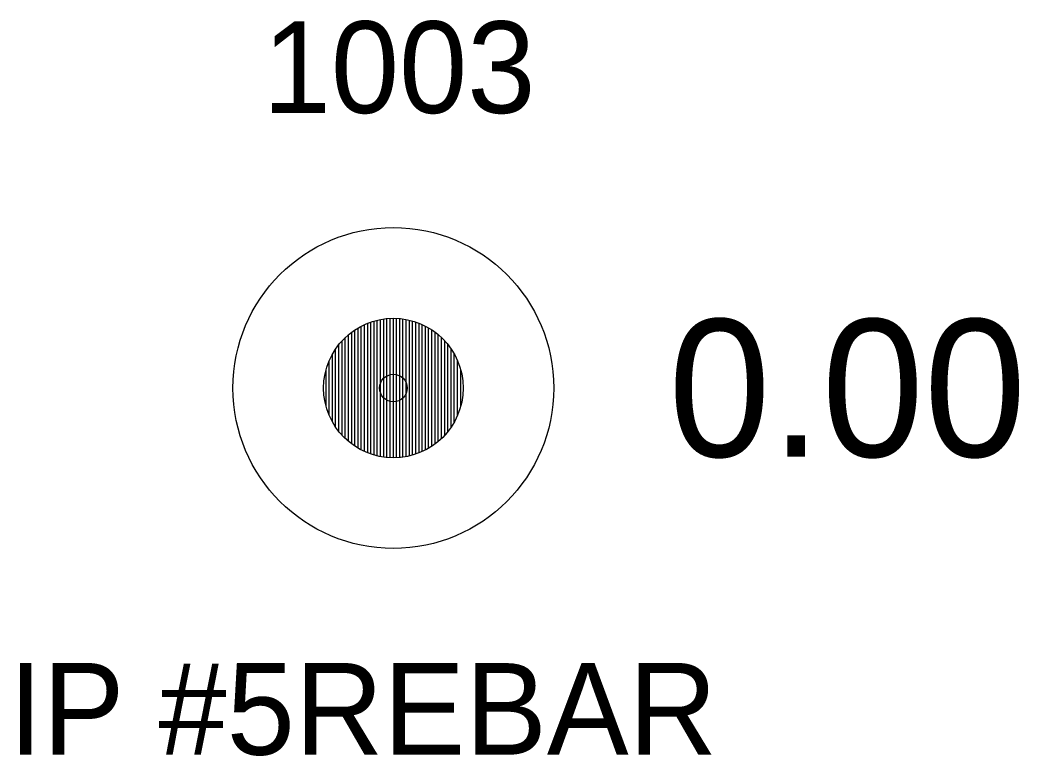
# Model space of a CAD drawing. Extents: x 2449052 to 2452984, y 1012343 to 1015262.
# Drawn here: x 2449337.72 to 2449348.62, y 1012428.52 to 1012436.55 of the extents above; entities that cross this region are included whole.
import ezdxf

# ---------------------------------------------------------------- set-up
doc = ezdxf.new("R2010")
doc.units = 0
for name, color, linetype in [('RD_EX_DV_Prop_txCode', 7, 'Continuous'), ('RD_EX_DV_PropPin', 7, 'Continuous'), ('RD_EX_TX_DV_Prop_ELEV', 7, 'Continuous'), ('RD_SMD_Locator', 7, 'Continuous')]:
    doc.layers.add(name, color=color, linetype=linetype)

msp = doc.modelspace()

# ---------------------------------------------------------------- linework, layer by layer
at = {"layer": 'RD_EX_DV_PropPin'}
for p, q in [((2449341.79, 1012431.773), (2449341.79, 1012433.295)), ((2449341.405, 1012431.877), (2449341.405, 1012433.19)), ((2449341.44, 1012431.858), (2449341.44, 1012433.209)), ((2449341.475, 1012431.841), (2449341.475, 1012433.227)), ((2449341.51, 1012431.826), (2449341.51, 1012433.241)), ((2449341.545, 1012431.813), (2449341.545, 1012433.254)), ((2449341.58, 1012431.802), (2449341.58, 1012433.265)), ((2449341.615, 1012431.793), (2449341.615, 1012433.274)), ((2449341.65, 1012431.786), (2449341.65, 1012433.282)), ((2449341.685, 1012431.78), (2449341.685, 1012433.288)), ((2449341.72, 1012431.776), (2449341.72, 1012433.292)), ((2449341.755, 1012431.774), (2449341.755, 1012433.294)), ((2449341.825, 1012431.774), (2449341.825, 1012433.294)), ((2449341.86, 1012431.776), (2449341.86, 1012433.292)), ((2449341.895, 1012431.78), (2449341.895, 1012433.288)), ((2449341.93, 1012431.786), (2449341.93, 1012433.282)), ((2449341.965, 1012431.793), (2449341.965, 1012433.274)), ((2449342, 1012431.802), (2449342, 1012433.265)), ((2449342.035, 1012431.813), (2449342.035, 1012433.254)), ((2449342.07, 1012431.826), (2449342.07, 1012433.241)), ((2449342.105, 1012431.841), (2449342.105, 1012433.227)), ((2449342.14, 1012431.858), (2449342.14, 1012433.209)), ((2449342.175, 1012431.877), (2449342.175, 1012433.19)), ((2449341.265, 1012431.983), (2449341.265, 1012433.085)), ((2449341.3, 1012431.952), (2449341.3, 1012433.116)), ((2449341.335, 1012431.924), (2449341.335, 1012433.144)), ((2449341.37, 1012431.899), (2449341.37, 1012433.168)), ((2449342.21, 1012431.899), (2449342.21, 1012433.168)), ((2449342.245, 1012431.924), (2449342.245, 1012433.144)), ((2449342.28, 1012431.952), (2449342.28, 1012433.116)), ((2449342.315, 1012431.983), (2449342.315, 1012433.085)), ((2449341.195, 1012432.06), (2449341.195, 1012433.008)), ((2449341.23, 1012432.019), (2449341.23, 1012433.049)), ((2449342.35, 1012432.019), (2449342.35, 1012433.049)), ((2449342.385, 1012432.06), (2449342.385, 1012433.008)), ((2449341.125, 1012432.164), (2449341.125, 1012432.903)), ((2449341.16, 1012432.107), (2449341.16, 1012432.96)), ((2449342.42, 1012432.107), (2449342.42, 1012432.96)), ((2449342.455, 1012432.164), (2449342.455, 1012432.903)), ((2449341.09, 1012432.236), (2449341.09, 1012432.832)), ((2449342.49, 1012432.236), (2449342.49, 1012432.832)), ((2449341.055, 1012432.338), (2449341.055, 1012432.73)), ((2449342.525, 1012432.338), (2449342.525, 1012432.73))]:
    msp.add_line(p, q, dxfattribs=at)
for radius in [1.75, 0.761]:
    msp.add_circle((2449341.79, 1012432.534), radius, dxfattribs=at)
at = {"layer": 'RD_SMD_Locator'}
msp.add_circle((2449341.79, 1012432.534), 0.15, dxfattribs=at)

# ---------------------------------------------------------------- texts
at = {"layer": 'RD_EX_DV_Prop_txCode'}
for s, p in [('1003', (2449340.365, 1012435.534)), ('IP #5REBAR', (2449337.593, 1012428.534))]:
    msp.add_text(s, height=1, dxfattribs=at).set_placement(p)
at = {"layer": 'RD_EX_TX_DV_Prop_ELEV'}
msp.add_text('0.00', height=1.5, dxfattribs=at).set_placement((2449344.79, 1012431.784))

doc.saveas('drawing.dxf')
